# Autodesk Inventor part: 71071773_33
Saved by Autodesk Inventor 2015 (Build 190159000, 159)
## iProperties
Created: 2019-12
Part Number: 71071773_33
Checked By: TraceParts S.A.
Material: Generic
Catalog Web Link: www.traceparts.com
Document SubType Name: Modeling
Designer: TraceParts
Density: 1 g/cm^3
Appearance: Default
Company: TraceParts S.A.
Author: TraceParts
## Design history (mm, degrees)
feature "71071773_33.ipt"
body "Solid1"
